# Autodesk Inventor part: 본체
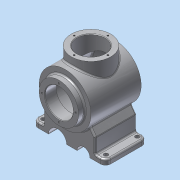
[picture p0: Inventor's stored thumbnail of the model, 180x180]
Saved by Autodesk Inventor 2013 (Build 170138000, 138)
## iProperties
Created: 2018-08
Part Number: 본체
Material: 알루미늄 6061
Document SubType Name: Modeling
Designer: Administrator
Density: 2.71 g/cm^3
Mass: 1888.22 g
Surface Area: 1092.87 cm^2
Volume: 696.76 cm^3
Author: Administrator
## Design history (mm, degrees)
sketch "스케치2"
  geometry: L1 (-70, 40)-(70, 40); L2 (70, 40)-(70, -40); L3 (70, -40)-(-70, -40); L4 (-70, -40)-(-70, 40); L5 (-70, 40)-(70, -40); L6 (70, 40)-(-70, -40); 1 further point
  constraints: 12 end point, 2 midpoint, 2 parallel, 1 horizontal, 1 perpendicular
  dimensions: "d0" = 140 distance of L2.end L3.end; "d1" = 80 distance of L1.end L2.end
extrude "돌출1" new body sketch "스케치2" distance "d2" = 10; taper "d3" = 0 deg
fillet "모깎기1" dims "d4" = 10
sketch "스케치3"
  geometry: L1 (0, 30)-(0, -30) reference; L2 (82, 60)-(82, -60); L3 (120, 60)-(120, 48); L4 (120, 48)-(132, 48); L5 (132, 48)-(132, -48.671); L6 (120, 60)-(82, 60); A1 r 116 centre (82, 56) between (82, -60) and (132, -48.671); 1 further point
  constraints: 10 end point, 2 parallel, 2 perpendicular, 2 point on circle, 1 centre point, 1 horizontal alignment, 1 point on line
  dimensions: "d6" = 120 distance of L2.start L2.end; "d7" = 60 vertical distance of point (0, 0) L2.start; "d8" = 82 distance between parallel lines of L1 L2; "d9" = 76 diameter of L3 L2; "d10" = 100 diameter of L5 L2; "d11" = 12 distance of L3.start L3.end; "d12" = 116 radius of A1
revolve "회전1" sketch "스케치3" stored, may be unused: angle "d13" = 90 deg
sketch "스케치4"
  geometry: L1 (44, 60)-(120, 60) reference; L2 (109, 60)-(109, 38); L3 (109, 38)-(122, 38); L4 (122, 38)-(122, -42.163); L5 (82, 60)-(82, -60); L6 (109, 60)-(82, 60); A1 r 116 centre (82, 56) between (32, -48.671) and (132, -48.671) reference; A2 r 106 centre (82, 56) between (82, -50) and (122, -42.163); 1 further point
  constraints: 10 end point, 3 perpendicular, 3 point on circle, 2 point on line, 1 centre point, 1 midpoint, 1 parallel
  dimensions: "d14" = 54 diameter of L2 L5; "d16" = 22 distance of L2.start L2.end; "d17" = 80 diameter of L4 L5; "d18" = 10 radial gap between concentric circles of A1 A2
revolve "회전2" sketch "스케치4" stored, may be unused: angle "d19" = 90 deg
node "작업 평면1"
chamfer "모따기1" distance "d41" = 1; stored, may be unused: second distance "d42" = 2, angle "d43" = 45 deg
sketch "스케치9"
  geometry: C1 r 38 at (0, 0) reference; 2 further points
  constraints: 1 vertical alignment
  dimensions: "d44" = 32.5 distance of C1.centre point (0, 32.5)
hole "구멍1" sketch "스케치9" at (0, 32.5) diameter "d45" = 3.242; stored, may be unused: countersink angle "d49" = 90 deg, drill point angle "d51" = 118 deg; dims "d46" = 8, "d47" = 4, "d48" = 2, "d50" = 10
fillet "모깎기3" dims "d66" = 3
fillet "모깎기4" dims "d67" = 3
node "작업 평면2"
sketch "스케치13"
  geometry: L1 (60, 0)-(-60, 0) reference; C1 r 32.5 at (0, 82); 1 further point
  constraints: 1 centre point, 1 other
  dimensions: "d73" = 65 diameter of C1; "d74" = 82 distance from line of L1 C1.centre; "d75" = 101.60709 distance of L1.start C1.centre
feature "엠보싱1" sketch "스케치13" dims "d0" = 140, "d1" = 80, "d6" = 120, "d7" = 60, "d8" = 82, "d9" = 76, "d10" = 100, "d11" = 12, "d12" = 116, "d76" = 0.5, "d77" = 0
sketch "스케치15"
  geometry: L1 (0, 10)-(120, 10) reference; L2 (-10, 10)-(-10, 0) reference; L3 (130, 0)-(130, 10) reference; L4 (19.696, 52.41)-(10, 38.563); L5 (110, 38.563)-(100.304, 52.41); L6 (10, 38.563)-(10, 10); L7 (120, 10)-(0, 10) reference; L8 (110, 38.563)-(110, 10); L9 (10, 10)-(110, 10); A1 r 50 centre (60, 82) between (100.304, 52.41) and (19.696, 52.41) reference; A2 r 50 centre (60, 82) between (19.696, 52.41) and (100.304, 52.41); 1 further point
  constraints: 10 end point, 4 point on circle, 2 perpendicular, 2 point on line, 1 centre point, 1 collinear, 1 parallel
  dimensions: "d82" = 35 deg angle of L4 L2; "d83" = 20 distance from line of L6.end L2; "d84" = 20 distance between parallel lines of L3 L8; "d85" = 35 deg angle of L3 L5; "d86" = 0 distance from line of L3.end L5
extrude "돌출4" join sketch "스케치15" distance "d87" = 80; taper "d88" = 0 deg
sketch "스케치16"
  geometry: L1 (120, 0)-(0, 0) reference; C1 r 17.5 at (37.5, 0); 1 further point
  constraints: 1 centre point, 1 point on line
  dimensions: "d89" = 17.5 radius of C1; "d90" = 22.5 distance of C1.centre point (60, 0)
extrude "돌출5" cut sketch "스케치16" stored distance "d91" = 80; taper "d92" = 0 deg
sketch "스케치17"
  geometry: L1 (0, 0)-(-65, 0) reference; C1 r 12.5 at (-32.5, 0); 1 further point
  constraints: 1 centre point, 1 midpoint
  dimensions: "d93" = 12.5 radius of C1; "d94" = 27.5 distance of C1.centre point (-60, 0)
extrude "돌출6" cut sketch "스케치17" stored distance "d95" = 80; taper "d96" = 0 deg
fillet "모깎기5" dims "d97" = 3
fillet "모깎기6" dims "d98" = 3
fillet "모깎기7" dims "d99" = 3
fillet "모깎기8" dims "d100" = 3
fillet "모깎기9" dims "d101" = 3
sketch "스케치18"
  geometry: L1 (-60, 37)-(-53, 37) reference; L2 (-67, -30)-(-67, 30) reference; L3 (-53, -37)-(-60, -37) reference; L4 (-53, 37)-(-53, -37) reference; A1 r 7 centre (-60, 30) between (-60, 37) and (-67, 30) reference; A2 r 7 centre (-60, -30) between (-67, -30) and (-60, -37) reference; 5 further points
  constraints: 2 coincident
hole "구멍3" sketch "스케치18" at (-60, 30), (-60, -30), (60, -28.996), (60, 31.223) diameter "d102" = 8; stored, may be unused: countersink angle "d106" = 90 deg, drill point angle "d108" = 0 deg; dims "d103" = 6, "d104" = 4, "d105" = 2, "d107" = 8
sketch "스케치19"
  geometry: L1 (-50, 48)-(50, 48) reference; C1 r 38 at (0, -2); 1 further point
  constraints: 1 centre point, 1 vertical alignment
  dimensions: "d109" = 76 diameter of C1; "d110" = 50 distance from line of C1.centre L1
extrude "돌출7" join sketch "스케치19" stored distance "d111" = 80; taper "d112" = 0 deg
sketch "스케치20"
  geometry: C1 r 38 at (0, 0) reference; C2 r 27 at (0, 0); 1 further point
  constraints: 1 centre point, 1 coincident
  dimensions: "d113" = 54 diameter of C2
extrude "돌출8" cut sketch "스케치20" distance "d114" = 80; taper "d115" = 0 deg
sketch "스케치21"
  geometry: C1 r 27 at (0, 0) reference; 2 further points
  constraints: 1 vertical alignment
  dimensions: "d116" = 32.5 distance of C1.centre point (0, 32.5)
hole "구멍4" sketch "스케치21" at (0, 32.5) diameter "d117" = 3.242; stored, may be unused: countersink angle "d121" = 90 deg, drill point angle "d123" = 118 deg; dims "d118" = 8, "d119" = 4, "d120" = 2, "d122" = 10
chamfer "모따기2" distance "d127" = 1; stored, may be unused: second distance "d128" = 2, angle "d129" = 45 deg
fillet "모깎기10" dims "d130" = 3
node "솔리드1"
pattern_circular "원형 패턴1" dims angle "d53" = 360 deg
pattern_circular "원형 패턴3" dims angle "d125" = 360 deg
node "투영된 루프2"
other parameters: "d34" = 147
